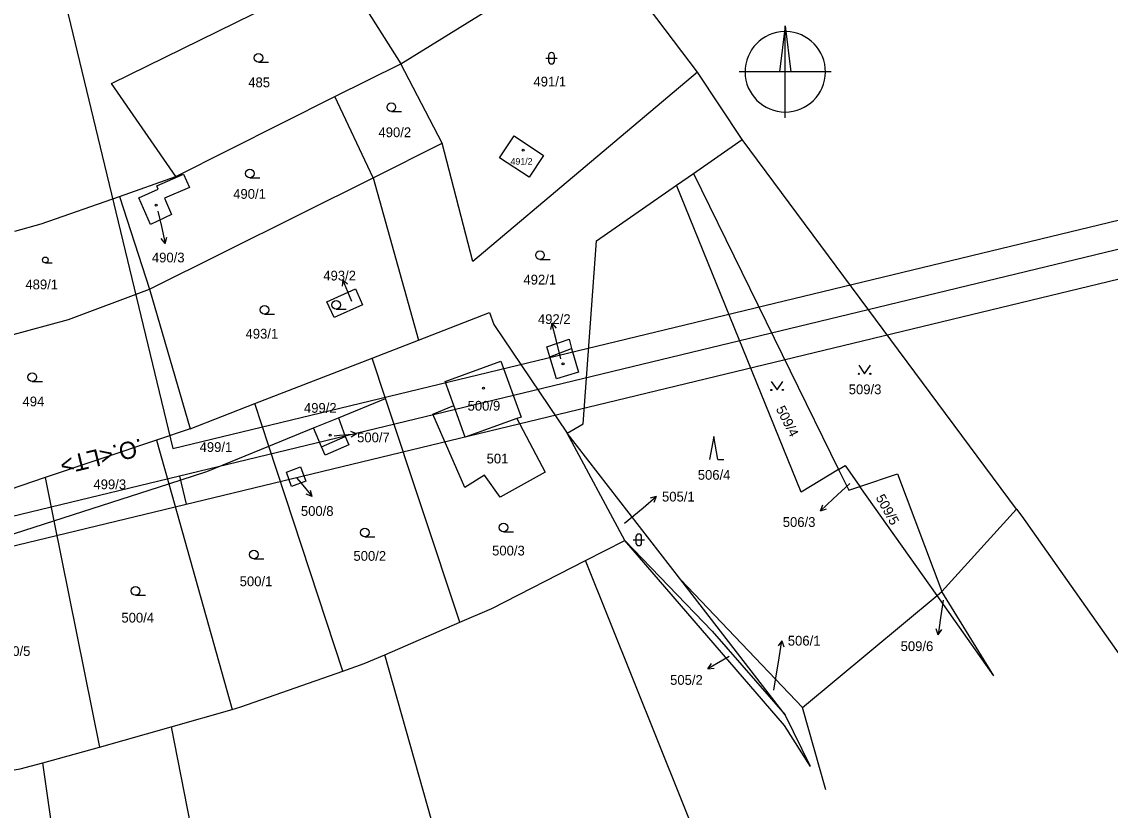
# Model space of a CAD drawing. Extents: x -738085 to -734306, y -1122197 to -1119753.
# Drawn here: x -735309.7 to -735120.1, y -1120523.6 to -1120386.3 of the extents above; entities that cross this region are included whole.
import ezdxf

# ---------------------------------------------------------------- set-up
doc = ezdxf.new("R2010")
doc.units = 0
for name, color, linetype in [('Hranice parcel', 7, 'Continuous'), ('Parcelní čísla', 7, 'Continuous'), ('Pop  PČ popisy', 7, 'Continuous'), ('Vnitřní kresba', 7, 'Continuous'), ('Vrstva 1', 7, 'Continuous'), ('Značky budov', 7, 'Continuous'), ('Značky kultur', 7, 'Continuous')]:
    doc.layers.add(name, color=color, linetype=linetype)

msp = doc.modelspace()

# ---------------------------------------------------------------- linework, layer by layer
at = {"layer": 'Hranice parcel'}
for p, q in [((-735243.71, -1120393.6), (-735209.2, -1120372.29)), ((-735192.01, -1120395.09), (-735209.2, -1120372.29)), ((-735192.01, -1120395.09), (-735209.2, -1120372.29)), ((-735253.96, -1120377.31), (-735243.71, -1120393.6)), ((-735255.18, -1120399.31), (-735243.71, -1120393.6)), ((-735236.48, -1120407.46), (-735243.71, -1120393.6)), ((-735184.26, -1120406.79), (-735192.01, -1120395.09)), ((-735184.26, -1120406.79), (-735192.01, -1120395.09)), ((-735282.89, -1120413.25), (-735255.18, -1120399.31)), ((-735248.5, -1120413.45), (-735255.18, -1120399.31)), ((-735248.5, -1120413.45), (-735236.48, -1120407.46)), ((-735192.71, -1120412.69), (-735184.26, -1120406.79)), ((-735136.45, -1120471.14), (-735184.26, -1120406.79)), ((-735136.45, -1120471.14), (-735184.26, -1120406.79)), ((-735292.69, -1120416.69), (-735282.89, -1120413.25)), ((-735287.43, -1120432.85), (-735248.5, -1120413.45)), ((-735248.5, -1120413.45), (-735240.61, -1120441.72)), ((-735195.69, -1120414.77), (-735192.71, -1120412.69)), ((-735192.71, -1120412.69), (-735167.46, -1120464.22)), ((-735209.63, -1120424.42), (-735195.69, -1120414.77)), ((-735306.34, -1120421.48), (-735292.69, -1120416.69)), ((-735292.69, -1120416.69), (-735287.43, -1120432.85)), ((-735310.9, -1120422.76), (-735306.34, -1120421.48)), ((-735287.43, -1120432.85), (-735280.35, -1120457.14)), ((-735227.5, -1120439.02), (-735214.69, -1120457.9)), ((-735248.68, -1120444.85), (-735240.61, -1120441.72)), ((-735269.09, -1120452.77), (-735248.68, -1120444.85)), ((-735246.34, -1120451.88), (-735248.68, -1120444.85)), ((-735254.54, -1120455.23), (-735246.34, -1120451.88)), ((-735233.39, -1120490.84), (-735246.34, -1120451.88)), ((-735280.35, -1120457.14), (-735269.09, -1120452.77)), ((-735266.65, -1120460.17), (-735269.09, -1120452.77)), ((-735258.92, -1120457.01), (-735254.54, -1120455.23)), ((-735280.35, -1120457.14), (-735286.24, -1120459.13)), ((-735266.65, -1120460.17), (-735258.92, -1120457.01)), ((-735194.9, -1120483.48), (-735214.69, -1120457.9)), ((-735204.69, -1120476.58), (-735214.69, -1120457.9)), ((-735286.24, -1120459.13), (-735305.6, -1120465.65)), ((-735286.24, -1120459.13), (-735284.11, -1120466.72)), ((-735253.76, -1120499.34), (-735266.65, -1120460.17)), ((-735305.6, -1120465.65), (-735319.23, -1120470.25)), ((-735305.6, -1120465.65), (-735304.09, -1120473.16)), ((-735304.09, -1120473.16), (-735284.11, -1120466.72)), ((-735284.11, -1120466.72), (-735273.08, -1120506.03)), ((-735150.29, -1120486.2), (-735163.73, -1120467.19)), ((-735149.45, -1120485.5), (-735136.45, -1120471.14)), ((-735304.09, -1120473.16), (-735296.16, -1120512.61)), ((-735211.51, -1120480.08), (-735204.69, -1120476.58)), ((-735176.75, -1120506.95), (-735194.9, -1120483.48)), ((-735173.71, -1120505.66), (-735194.9, -1120483.48)), ((-735173.71, -1120505.66), (-735150.29, -1120486.2)), ((-735150.29, -1120486.2), (-735149.45, -1120485.5)), ((-735140.42, -1120500.16), (-735150.29, -1120486.2)), ((-735140.42, -1120500.16), (-735149.45, -1120485.5)), ((-735246.5, -1120496.5), (-735233.39, -1120490.84)), ((-735283.7, -1120509.06), (-735273.08, -1120506.03)), ((-735172.33, -1120515.97), (-735176.75, -1120506.95)), ((-735169.66, -1120520), (-735173.71, -1120505.66)), ((-735296.16, -1120512.61), (-735283.7, -1120509.06)), ((-735306.01, -1120515.3), (-735296.16, -1120512.61))]:
    msp.add_line(p, q, dxfattribs=at)
for points in [[(-735282.89, -1120413.25), (-735294.07, -1120397.05), (-735253.96, -1120377.31)], [(-735192.01, -1120395.09), (-735231.12, -1120428.06), (-735236.48, -1120407.46)], [(-735223.96, -1120406.17), (-735218.84, -1120409.56), (-735221.34, -1120413.34), (-735226.51, -1120410), (-735223.96, -1120406.17)], [(-735286.19, -1120414.89), (-735281.55, -1120412.82), (-735280.52, -1120415.13), (-735284.84, -1120417.03), (-735283.6, -1120419.87), (-735287.27, -1120421.58), (-735289.33, -1120416.97), (-735285.94, -1120415.46), (-735286.19, -1120414.89)], [(-735167.46, -1120464.22), (-735173.96, -1120468.21), (-735195.69, -1120414.77)], [(-735214.69, -1120457.9), (-735211.91, -1120456.28), (-735209.63, -1120424.42)], [(-735325.59, -1120444.65), (-735301.59, -1120438.14), (-735287.43, -1120432.85)], [(-735250.35, -1120435.58), (-735255.3, -1120437.81), (-735256.55, -1120435.04), (-735251.6, -1120432.78), (-735250.35, -1120435.58)], [(-735240.61, -1120441.72), (-735228.25, -1120436.92), (-735227.5, -1120439.02)], [(-735218.28, -1120442.9), (-735214.36, -1120441.54), (-735213.94, -1120443.17), (-735212.75, -1120447.32), (-735216.6, -1120448.48), (-735217.76, -1120444.64), (-735218.28, -1120442.9)], [(-735234.48, -1120453.11), (-735235.99, -1120448.9), (-735226.28, -1120445.37), (-735222.73, -1120455.13), (-735223.46, -1120455.39)], [(-735223.46, -1120455.39), (-735218.56, -1120464.68), (-735226.39, -1120469.04), (-735229.13, -1120465.26), (-735232.56, -1120467.36), (-735238.11, -1120454.62), (-735234.48, -1120453.11)], [(-735223.46, -1120455.39), (-735232.5, -1120458.6), (-735234.48, -1120453.11)], [(-735254.54, -1120455.23), (-735253.38, -1120458.5), (-735252.75, -1120459.96), (-735256.87, -1120461.74), (-735257.5, -1120460.29), (-735258.92, -1120457.01)], [(-735284.11, -1120466.72), (-735277.48, -1120464.59), (-735266.65, -1120460.17)], [(-735167.46, -1120464.22), (-735166.32, -1120463.52), (-735163.73, -1120467.19)], [(-735263.61, -1120464.7), (-735261.15, -1120463.8), (-735260.24, -1120466.3), (-735262.71, -1120467.19), (-735263.61, -1120464.7)], [(-735167.46, -1120464.22), (-735165.68, -1120467.84), (-735163.73, -1120467.19)], [(-735163.73, -1120467.19), (-735157.2, -1120465), (-735149.45, -1120485.5)], [(-735136.45, -1120471.14), (-735135.53, -1120472.38), (-735095.05, -1120529.74), (-735037.29, -1120611.91), (-735033.19, -1120617.24)], [(-735136.45, -1120471.14), (-735135.53, -1120472.38), (-735095.05, -1120529.74), (-735037.29, -1120611.91), (-735033.19, -1120617.24)], [(-735325.23, -1120478.92), (-735317.9, -1120477.6), (-735304.09, -1120473.16)], [(-735172.33, -1120515.97), (-735176.87, -1120508.81), (-735204.69, -1120476.58)], [(-735204.69, -1120476.58), (-735189.44, -1120492.41), (-735176.75, -1120506.95)], [(-735233.39, -1120490.84), (-735227.84, -1120488.44), (-735211.51, -1120480.08)], [(-735147.01, -1120637.76), (-735190.57, -1120532.29), (-735211.51, -1120480.08)], [(-735253.76, -1120499.34), (-735250.05, -1120498.03), (-735246.5, -1120496.5)], [(-735197.99, -1120653.57), (-735232.34, -1120546.41), (-735246.5, -1120496.5)], [(-735273.08, -1120506.03), (-735271.53, -1120505.59), (-735253.76, -1120499.34)], [(-735283.7, -1120509.06), (-735263.64, -1120611.21), (-735252.85, -1120663.28)], [(-735321.15, -1120518.14), (-735309.98, -1120516.38), (-735306.01, -1120515.3)], [(-735288.34, -1120621.9), (-735292.8, -1120607.98), (-735306.01, -1120515.3)]]:
    msp.add_lwpolyline(points, dxfattribs=at)
at = {"layer": 'Pop  PČ popisy'}
for p, q in [((-735286.02, -1120419.3), (-735285.38, -1120421.97)), ((-735285.38, -1120421.97), (-735284.7, -1120424.89)), ((-735284.7, -1120424.89), (-735284.44, -1120423.81)), ((-735284.7, -1120424.89), (-735285.42, -1120424.03)), ((-735253.81, -1120431.23), (-735253.88, -1120432.34)), ((-735252.64, -1120433.99), (-735253.81, -1120431.23)), ((-735253.81, -1120431.23), (-735252.96, -1120431.95)), ((-735252.2, -1120435.02), (-735252.64, -1120433.99)), ((-735217.37, -1120438.78), (-735217.61, -1120439.87)), ((-735216.64, -1120441.69), (-735217.37, -1120438.78)), ((-735217.37, -1120438.78), (-735216.64, -1120439.63)), ((-735215.81, -1120445), (-735216.64, -1120441.69)), ((-735251.38, -1120458.04), (-735252.41, -1120457.61)), ((-735255.28, -1120458.38), (-735254.37, -1120458.25)), ((-735254.37, -1120458.25), (-735251.38, -1120458.04)), ((-735251.38, -1120458.04), (-735252.34, -1120458.61)), ((-735261.77, -1120465.74), (-735261.04, -1120466.64)), ((-735261.04, -1120466.64), (-735259.15, -1120468.97)), ((-735165.49, -1120466.66), (-735168.42, -1120469.37)), ((-735259.15, -1120468.97), (-735260.17, -1120468.51)), ((-735259.15, -1120468.97), (-735259.39, -1120467.88)), ((-735201.5, -1120470.9), (-735199.2, -1120468.97)), ((-735199.2, -1120468.97), (-735200.29, -1120469.23)), ((-735199.2, -1120468.97), (-735199.65, -1120470)), ((-735204.71, -1120473.59), (-735201.5, -1120470.9)), ((-735168.42, -1120469.37), (-735170.61, -1120471.42)), ((-735170.61, -1120471.42), (-735170.22, -1120470.37)), ((-735170.61, -1120471.42), (-735169.54, -1120471.1)), ((-735149.25, -1120487), (-735149.68, -1120490.05)), ((-735149.68, -1120490.05), (-735150.1, -1120493.02)), ((-735150.1, -1120493.02), (-735150.45, -1120491.96)), ((-735150.1, -1120493.02), (-735149.46, -1120492.1)), ((-735177.31, -1120494.05), (-735177.96, -1120494.96)), ((-735177.78, -1120497.01), (-735177.31, -1120494.05)), ((-735177.31, -1120494.05), (-735176.97, -1120495.11)), ((-735187.63, -1120497.42), (-735190.23, -1120498.92)), ((-735186.53, -1120496.79), (-735187.63, -1120497.42)), ((-735178.7, -1120502.64), (-735177.78, -1120497.01)), ((-735190.23, -1120498.92), (-735189.61, -1120497.99)), ((-735190.23, -1120498.92), (-735189.11, -1120498.85))]:
    msp.add_line(p, q, dxfattribs=at)
at = {"layer": 'Vnitřní kresba'}
for p, q in [((-735217.76, -1120444.64), (-735213.94, -1120443.17)), ((-735257.5, -1120460.29), (-735253.38, -1120458.5))]:
    msp.add_line(p, q, dxfattribs=at)
at = {"layer": 'Vrstva 1'}
for p, q in [((-735176.74, -1120387.01), (-735177.74, -1120395.01)), ((-735176.74, -1120403.01), (-735176.74, -1120387.01)), ((-735168.74, -1120395.01), (-735184.74, -1120395.01)), ((-735282.24, -1120465.42), (-735281.07, -1120470.27))]:
    msp.add_line(p, q, dxfattribs=at)
for points in [[(-734534.27, -1119984.39), (-735554.91, -1120230.88), (-735485.2, -1120519.57), (-734464.55, -1120273.08)], [(-734470.58, -1120269.4), (-735481.51, -1120513.53), (-735548.88, -1120234.56), (-734537.95, -1119990.43)], [(-734541.63, -1119996.45), (-735348.44, -1120191.3), (-735283.42, -1120460.56), (-734476.61, -1120265.71)], [(-735176.74, -1120387.01), (-735175.74, -1120395.01), (-735176.74, -1120395.01)]]:
    msp.add_lwpolyline(points, close=True, dxfattribs=at)
msp.add_arc((-735176.74, -1120395.01), 7, 91.0243, 88.9757, dxfattribs=at)
at = {"layer": 'Značky budov'}
for centre in [(-735222.36, -1120408.67), (-735286.31, -1120418.24), (-735215.44, -1120445.86), (-735229.3, -1120450.1), (-735256, -1120458.27)]:
    msp.add_circle(centre, 0.175, dxfattribs=at)
at = {"layer": 'Značky kultur'}
for p, q in [((-735268.48, -1120393.34), (-735266.73, -1120393.34)), ((-735218.45, -1120392.65), (-735216.45, -1120392.65)), ((-735217.95, -1120392.15), (-735217.95, -1120393.15)), ((-735216.95, -1120393.15), (-735216.95, -1120392.15)), ((-735245.34, -1120401.9), (-735243.59, -1120401.9)), ((-735269.99, -1120413.48), (-735268.24, -1120413.48)), ((-735305.59, -1120428.27), (-735304.42, -1120428.27)), ((-735219.45, -1120427.7), (-735217.7, -1120427.7)), ((-735254.93, -1120436.32), (-735253.18, -1120436.32)), ((-735267.42, -1120437.18), (-735265.67, -1120437.18)), ((-735307.87, -1120448.93), (-735306.12, -1120448.93)), ((-735189.2, -1120458.48), (-735189.95, -1120462.48)), ((-735188.45, -1120462.48), (-735189.2, -1120458.48)), ((-735188.45, -1120462.48), (-735187.45, -1120462.48)), ((-735249.95, -1120475.98), (-735248.2, -1120475.98)), ((-735225.82, -1120475.11), (-735224.07, -1120475.11)), ((-735203.25, -1120476.49), (-735201.25, -1120476.49)), ((-735202.75, -1120475.99), (-735202.75, -1120476.99)), ((-735201.75, -1120476.99), (-735201.75, -1120475.99)), ((-735269.3, -1120479.81), (-735267.55, -1120479.81)), ((-735289.9, -1120486.14), (-735288.15, -1120486.14))]:
    msp.add_line(p, q, dxfattribs=at)
for points in [[(-735163.91, -1120446.09), (-735162.91, -1120447.59), (-735161.91, -1120446.09)], [(-735179.17, -1120448.9), (-735178.17, -1120450.4), (-735177.17, -1120448.9)]]:
    msp.add_lwpolyline(points, dxfattribs=at)
for centre, radius in [((-735268.48, -1120392.59), 0.75), ((-735245.34, -1120401.15), 0.75), ((-735269.99, -1120412.73), 0.75), ((-735305.6, -1120427.77), 0.502), ((-735219.45, -1120426.95), 0.75), ((-735254.93, -1120435.57), 0.75), ((-735267.42, -1120436.43), 0.75), ((-735307.87, -1120448.18), 0.75), ((-735163.91, -1120447.59), 0.1), ((-735161.91, -1120447.59), 0.1), ((-735179.17, -1120450.4), 0.1), ((-735177.17, -1120450.4), 0.1), ((-735249.95, -1120475.23), 0.75), ((-735225.82, -1120474.36), 0.75), ((-735269.3, -1120479.06), 0.75), ((-735289.9, -1120485.39), 0.75)]:
    msp.add_circle(centre, radius, dxfattribs=at)
for centre, start, end in [((-735217.45, -1120392.15), 0, 180), ((-735217.45, -1120393.15), 180, 359.9879), ((-735202.25, -1120475.99), 0, 180), ((-735202.25, -1120476.99), 180, 359.9879)]:
    msp.add_arc(centre, 0.5, start, end, dxfattribs=at)

# ---------------------------------------------------------------- texts
at = {"layer": 'Parcelní čísla'}
for s, height, p in [('485', 1.7, (-735270.26, -1120397.7)), ('491/1', 1.7, (-735220.59, -1120397.56)), ('490/2', 1.7, (-735247.58, -1120406.39)), ('491/2', 1.14, (-735224.57, -1120411.18)), ('490/1', 1.7, (-735272.88, -1120417.12)), ('490/3', 1.7, (-735287.04, -1120428.19)), ('489/1', 1.7, (-735309.07, -1120432.88)), ('493/2', 1.7, (-735257.19, -1120431.34)), ('492/1', 1.7, (-735222.33, -1120432.04)), ('492/2', 1.7, (-735219.81, -1120438.92)), ('493/1', 1.7, (-735270.73, -1120441.46)), ('509/3', 1.7, (-735165.68, -1120451.14)), ('494', 1.7, (-735309.57, -1120453.25)), ('500/9', 1.7, (-735232.06, -1120454)), ('499/2', 1.7, (-735260.56, -1120454.37)), ('500/7', 1.7, (-735251.3, -1120459.51)), ('499/1', 1.7, (-735278.73, -1120461.19)), ('501', 1.7, (-735228.75, -1120463.19)), ('506/4', 1.7, (-735191.97, -1120466.03)), ('499/3', 1.7, (-735297.22, -1120467.68)), ('505/1', 1.7, (-735198.2, -1120469.82)), ('500/8', 1.7, (-735261.09, -1120472.32)), ('506/3', 1.7, (-735177.17, -1120474.24)), ('500/2', 1.7, (-735251.94, -1120480.14)), ('500/3', 1.7, (-735227.79, -1120479.21)), ('500/1', 1.7, (-735271.75, -1120484.56)), ('500/4', 1.7, (-735292.35, -1120490.89)), ('506/1', 1.7, (-735176.29, -1120494.9)), ('500/5', 1.7, (-735313.89, -1120496.71)), ('509/6', 1.7, (-735156.64, -1120495.85)), ('505/2', 1.7, (-735196.79, -1120501.73))]:
    msp.add_text(s, height=height, dxfattribs=at).set_placement(p)
for s, rotation, p in [('509/4', 297, (-735178.41, -1120453.68)), ('509/5', 299, (-735161.04, -1120469.14))]:
    msp.add_text(s, height=1.7, rotation=rotation, dxfattribs=at).set_placement(p)
at = {"layer": 'Vrstva 1'}
msp.add_text('.O.<LT>', height=3, rotation=193.5769, dxfattribs=at).set_placement((-735288.97, -1120458.82))

doc.saveas('drawing.dxf')
